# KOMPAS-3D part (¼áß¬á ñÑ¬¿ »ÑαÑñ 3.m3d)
File: created 06.04.2016 12:01:11, last saved 22.07.2016 16:03:08.
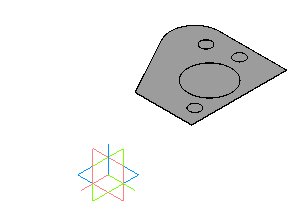
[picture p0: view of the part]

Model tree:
1. Эскиз:1
2. Операция выдавливания:1
     Толщина стенки 2 = 15; Расстояние 1 = 0.8; Расстояние 2 = 96.2519
3. Эскиз:2
4. Вырезать элемент выдавливания:1
     Толщина стенки 1 = 2; Толщина стенки 2 = 2; Расстояние 1 = 10
5. Эскиз:3
6. Вырезать элемент выдавливания:2
     Толщина стенки 1 = 2; Толщина стенки 2 = 2; Расстояние 1 = 10
7. Эскиз:4
8. Вырезать элемент выдавливания:3
     Толщина стенки 1 = 2; Толщина стенки 2 = 2; Расстояние 1 = 10
9. Эскиз:5
10. Вырезать элемент выдавливания:4
     Толщина стенки 1 = 2; Толщина стенки 2 = 2; Расстояние 1 = 0.4
11. Эскиз:6
12. Вырезать элемент выдавливания:5
     Толщина стенки 1 = 2; Толщина стенки 2 = 2; Расстояние 1 = 0.4
13. Эскиз:7
14. Вырезать элемент выдавливания:6
     Толщина стенки 1 = 2; Толщина стенки 2 = 2; Расстояние 1 = 10.4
